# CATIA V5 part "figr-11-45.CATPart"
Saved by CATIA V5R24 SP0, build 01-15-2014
Part number: Part1
Bounding box of the stored display mesh (mm): x -59 to 59, y -60 to 210, z -30 to 39.8
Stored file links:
  D:\KAVITA\CATIA V5-6R2014 Project_ Kavita\CATIA V5-6R2014_partfiles\Partfiles\c11_catia_v5-6r2014_prt\figr-11-45.CATPart
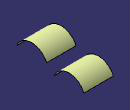
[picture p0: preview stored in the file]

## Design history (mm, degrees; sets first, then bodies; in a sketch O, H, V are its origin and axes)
AxisSystem1: origin (0, 0, 0), X (1, 0, 0), Y (0, 1, 0), Z (0, 0, 1)
AxisSystem2: origin (0, 150, -30), X (1, 0, 0), Y (0, 1, 0), Z (0, 0, 1)
Set1
  Extrude1: Element1 Sketch2, Lim1 59, Lim2 59, Direction yz-plane
  Sketch1 on yz-plane, origin (0, 0, 0), H (0, 1, 0), V (0, 0, 1)
    point P1 (150, -30)
  AxisToAxis1: ToTransfor Extrude1, AxisOrigin AxisSystem1, Axis AxisSystem2
Body1 (main body)
  Sketch2 on yz-plane, origin (0, 0, 0), H (0, 1, 0), V (0, 0, 1)
    arc A1 centre (0, -25) radius 65 from (-60, 0) to (60, 0) cw
    point P2 (-60, 0)
    point P3 (60, 0)
    coincidence: P2 H, P3 H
